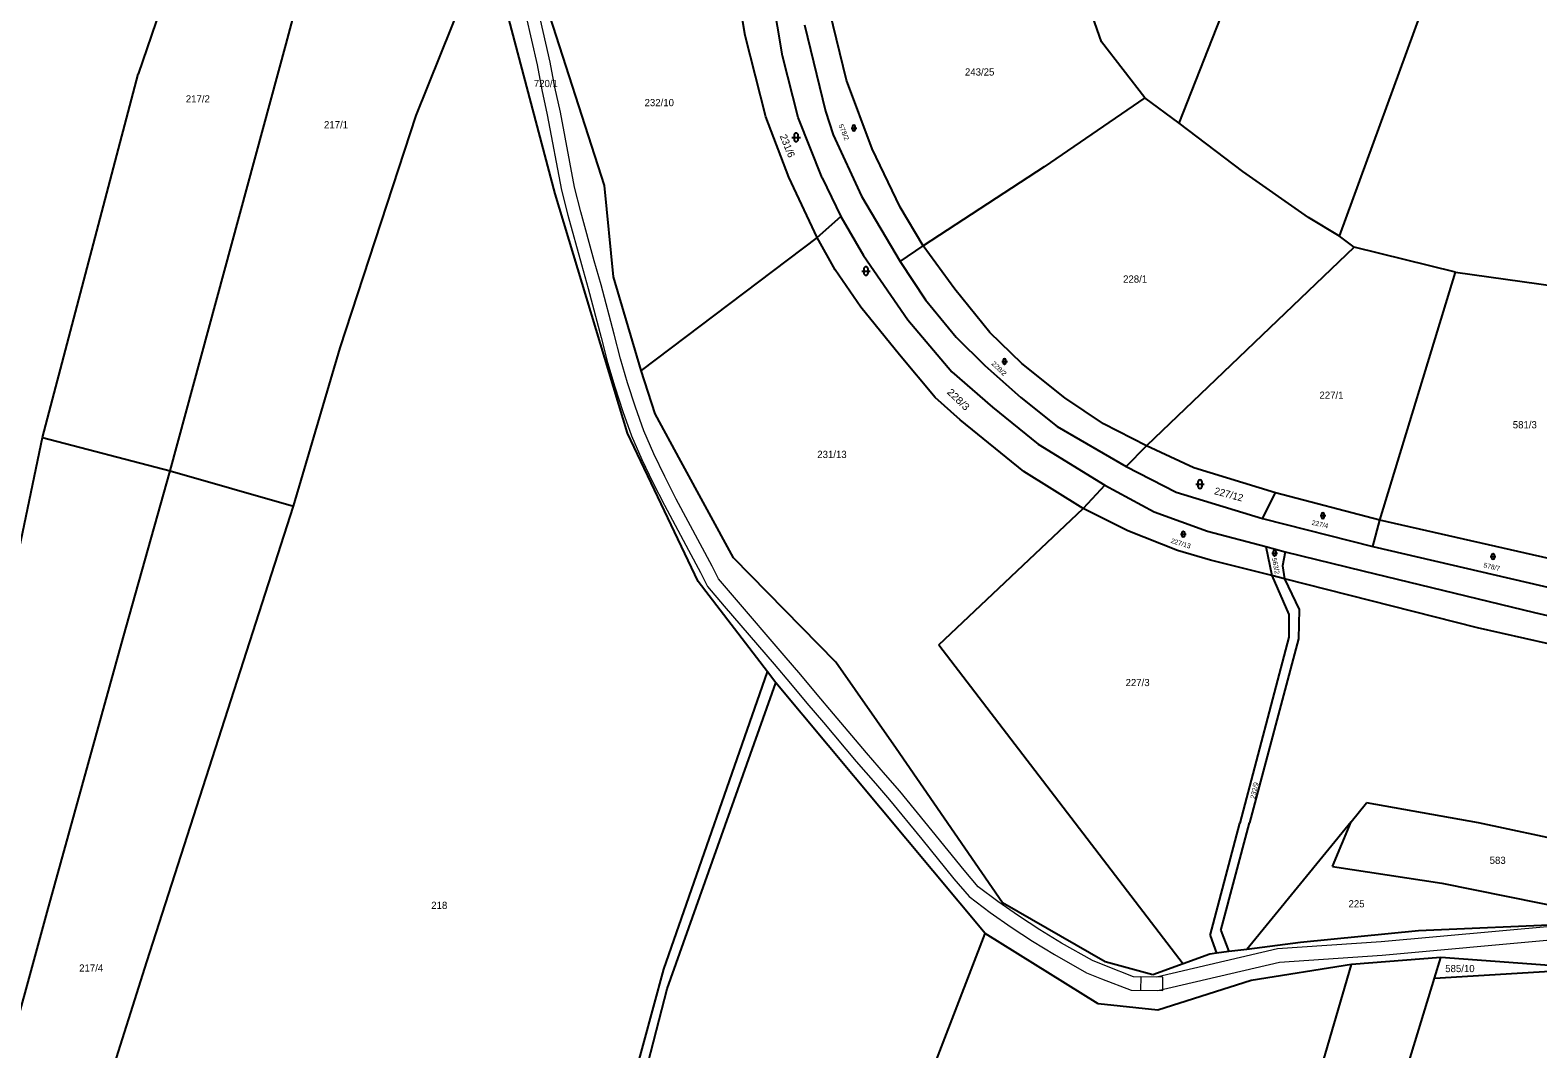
# Model space of a CAD drawing. Extents: x -701211 to -698780, y -1014269 to -1012378.
# Drawn here: x -701029.9 to -700673.2, y -1013179.3 to -1012938.3 of the extents above; entities that cross this region are included whole.
import ezdxf
from ezdxf.enums import TextEntityAlignment as Align

# ---------------------------------------------------------------- set-up
doc = ezdxf.new("R2010")
doc.units = 0
doc.header["$LTSCALE"] = 0.68
for name, color, linetype, lineweight in [('1', 7, 'Continuous', 25), ('13', 7, 'Continuous', 13), ('3', 7, 'Continuous', 25)]:
    doc.layers.add(name, color=color, linetype=linetype, lineweight=lineweight)
doc.layers.add('2', color=7, linetype='Continuous')

msp = doc.modelspace()

# ---------------------------------------------------------------- linework, layer by layer
at = {"layer": '1'}
for p, q in [((-700758.04, -1012960.3), (-700727.83, -1012883.45)), ((-700860.7, -1012939.55), (-700868.99, -1012890.01)), ((-700987.06, -1012897.76), (-701004.28, -1012948.73)), ((-700720.09, -1012987.07), (-700687.77, -1012898.43)), ((-700776.39, -1012941.06), (-700788.72, -1012906.25)), ((-700894, -1012975.02), (-700914.53, -1012911.43)), ((-700938.57, -1012958.49), (-700921.68, -1012916.49)), ((-700905.7, -1012977.03), (-700921.68, -1012916.49)), ((-700851.85, -1012944.35), (-700856.53, -1012916.78)), ((-700836.72, -1012950.14), (-700840.69, -1012933.93)), ((-700855.84, -1012958.82), (-700860.7, -1012939.55)), ((-700846.71, -1012937.05), (-700841.75, -1012957.5)), ((-700766.16, -1012954.34), (-700776.39, -1012941.06)), ((-700848.15, -1012958.95), (-700851.85, -1012944.35)), ((-701026.92, -1013034.65), (-701004.28, -1012948.73)), ((-700830.69, -1012966.36), (-700836.72, -1012950.14)), ((-700766.16, -1012954.34), (-700789.95, -1012970.64)), ((-700758.04, -1012960.3), (-700766.16, -1012954.34)), ((-700956.52, -1013013.46), (-700938.57, -1012958.49)), ((-700850.35, -1012973.06), (-700855.84, -1012958.82)), ((-700842.48, -1012973.27), (-700848.15, -1012958.95)), ((-700841.75, -1012957.5), (-700839.86, -1012963.08)), ((-700742.97, -1012971.7), (-700758.04, -1012960.3)), ((-700839.86, -1012963.08), (-700833.2, -1012977.59)), ((-700824.03, -1012980.14), (-700830.69, -1012966.36)), ((-700789.95, -1012970.64), (-700818.62, -1012989.33)), ((-700727.44, -1012982.58), (-700742.97, -1012971.7)), ((-700891.83, -1012996.63), (-700894, -1012975.02)), ((-700843.68, -1012987.38), (-700850.35, -1012973.06)), ((-700842.48, -1012973.27), (-700838.07, -1012982.37)), ((-700888.56, -1013033.61), (-700905.7, -1012977.03)), ((-700833.2, -1012977.59), (-700824.01, -1012993)), ((-700843.68, -1012987.38), (-700838.07, -1012982.37)), ((-700838.07, -1012982.37), (-700832.75, -1012991.62)), ((-700720.09, -1012987.07), (-700727.44, -1012982.58)), ((-700843.68, -1012987.38), (-700885.35, -1013018.79)), ((-700839.45, -1012995.03), (-700843.68, -1012987.38)), ((-700811.15, -1012999.6), (-700818.62, -1012989.33)), ((-700716.68, -1012989.67), (-700720.09, -1012987.07)), ((-700832.75, -1012991.62), (-700822.22, -1013006.85)), ((-700824.01, -1012993), (-700818.07, -1013002.06)), ((-700716.68, -1012989.67), (-700765.76, -1013036.63)), ((-700692.69, -1012995.55), (-700716.68, -1012989.67)), ((-700885.35, -1013018.79), (-700891.83, -1012996.63)), ((-700833.33, -1013003.86), (-700839.45, -1012995.03)), ((-700710.55, -1013054.2), (-700692.69, -1012995.55)), ((-700692.69, -1012995.55), (-700648.95, -1013001.61)), ((-700802.86, -1013009.78), (-700811.15, -1012999.6)), ((-700818.07, -1013002.06), (-700810.78, -1013010.89)), ((-700824.24, -1013015.12), (-700833.33, -1013003.86)), ((-700822.22, -1013006.85), (-700811.86, -1013019.09)), ((-700810.78, -1013010.89), (-700804.02, -1013017.65)), ((-700795.3, -1013017.17), (-700802.86, -1013009.78)), ((-700967.57, -1013050.91), (-700956.52, -1013013.46)), ((-700815.77, -1013025.2), (-700824.24, -1013015.12)), ((-700804.02, -1013017.65), (-700795.47, -1013025.22)), ((-700785.12, -1013025.28), (-700795.3, -1013017.17)), ((-700882.02, -1013029.05), (-700885.35, -1013018.79)), ((-700811.86, -1013019.09), (-700802.22, -1013027.47)), ((-700809.83, -1013030.51), (-700815.77, -1013025.2)), ((-700795.47, -1013025.22), (-700786.91, -1013032.07)), ((-700802.22, -1013027.47), (-700791.41, -1013036.21)), ((-700775.93, -1013031.4), (-700785.12, -1013025.28)), ((-700875.9, -1013040.22), (-700882.02, -1013029.05)), ((-700794.8, -1013042.67), (-700809.83, -1013030.51)), ((-700786.91, -1013032.07), (-700770.61, -1013041.53)), ((-700765.76, -1013036.63), (-700775.93, -1013031.4)), ((-701037.51, -1013084.94), (-701026.92, -1013034.65)), ((-701026.92, -1013034.65), (-700996.75, -1013042.57)), ((-700871.86, -1013068.73), (-700888.56, -1013033.61)), ((-700791.41, -1013036.21), (-700775.65, -1013045.94)), ((-700770.61, -1013041.53), (-700765.76, -1013036.63)), ((-700754.59, -1013041.86), (-700765.76, -1013036.63)), ((-701007.88, -1013082.07), (-700996.75, -1013042.57)), ((-700996.75, -1013042.57), (-700967.57, -1013050.91)), ((-700863.47, -1013063.1), (-700875.9, -1013040.22)), ((-700780.79, -1013051.47), (-700794.8, -1013042.67)), ((-700770.61, -1013041.53), (-700758.77, -1013047.55)), ((-700735.23, -1013047.71), (-700754.59, -1013041.86)), ((-700775.65, -1013045.94), (-700780.79, -1013051.47)), ((-700775.65, -1013045.94), (-700763.95, -1013052.25)), ((-700758.77, -1013047.55), (-700738.32, -1013053.85)), ((-700738.32, -1013053.85), (-700735.23, -1013047.71)), ((-700710.55, -1013054.2), (-700735.23, -1013047.71)), ((-701002.24, -1013158.7), (-700967.57, -1013050.91)), ((-700814.87, -1013083.67), (-700780.79, -1013051.47)), ((-700770.22, -1013056.72), (-700780.79, -1013051.47)), ((-700763.95, -1013052.25), (-700751.34, -1013056.84)), ((-700758.42, -1013061.4), (-700770.22, -1013056.72)), ((-700751.34, -1013056.84), (-700737.55, -1013060.42)), ((-700738.32, -1013053.85), (-700712.2, -1013060.43)), ((-700712.2, -1013060.43), (-700710.55, -1013054.2)), ((-700660.84, -1013065.55), (-700710.55, -1013054.2)), ((-700737.55, -1013060.42), (-700736.13, -1013067.31)), ((-700737.55, -1013060.42), (-700732.96, -1013061.68)), ((-700712.2, -1013060.43), (-700661.94, -1013072.14)), ((-700839.25, -1013087.78), (-700863.47, -1013063.1)), ((-700750.59, -1013063.65), (-700758.42, -1013061.4)), ((-700736.13, -1013067.31), (-700750.59, -1013063.65)), ((-700732.96, -1013061.68), (-700733.59, -1013065.02)), ((-700732.96, -1013061.68), (-700714.59, -1013066.21)), ((-700733.13, -1013068.07), (-700736.13, -1013067.31)), ((-700736.13, -1013067.31), (-700732.06, -1013076.53)), ((-700733.59, -1013065.02), (-700733.13, -1013068.07)), ((-700714.59, -1013066.21), (-700673.98, -1013076.04)), ((-700855.43, -1013090.08), (-700871.86, -1013068.73)), ((-700733.13, -1013068.07), (-700729.63, -1013075.36)), ((-700687.43, -1013079.64), (-700733.13, -1013068.07)), ((-700732.06, -1013076.53), (-700732.06, -1013081.85)), ((-700729.63, -1013075.36), (-700729.81, -1013082.3)), ((-700673.98, -1013076.04), (-700602.11, -1013092.88)), ((-701025.84, -1013146.92), (-701007.88, -1013082.07)), ((-700732.06, -1013081.85), (-700743.67, -1013125.89)), ((-700729.81, -1013082.3), (-700741.42, -1013125.8)), ((-700630.58, -1013092.65), (-700687.43, -1013079.64)), ((-700814.87, -1013083.67), (-700757.1, -1013159.17)), ((-700825.03, -1013108.22), (-700839.25, -1013087.78)), ((-700879.94, -1013160.4), (-700855.43, -1013090.08)), ((-700879.13, -1013165.07), (-700853.45, -1013092.71)), ((-700853.45, -1013092.71), (-700855.43, -1013090.08)), ((-700803.97, -1013151.99), (-700853.45, -1013092.71)), ((-700799.83, -1013144.7), (-700825.03, -1013108.22)), ((-700717.35, -1013125.54), (-700713.75, -1013121.04)), ((-700687.22, -1013125.82), (-700713.75, -1013121.04)), ((-700750.7, -1013152.46), (-700743.67, -1013125.89)), ((-700748.17, -1013151.29), (-700741.42, -1013125.8)), ((-700717.35, -1013125.54), (-700742.07, -1013155.75)), ((-700721.76, -1013136.17), (-700717.35, -1013125.54)), ((-700660.99, -1013131.4), (-700687.22, -1013125.82)), ((-700721.76, -1013136.17), (-700695.92, -1013140.04)), ((-700695.92, -1013140.04), (-700651.1, -1013149.11)), ((-700775.52, -1013158.66), (-700799.83, -1013144.7)), ((-701055.38, -1013254.89), (-701025.84, -1013146.92)), ((-700651.1, -1013149.11), (-700701.42, -1013151.36)), ((-700822.65, -1013200.55), (-700803.97, -1013151.99)), ((-700777.22, -1013168.6), (-700803.97, -1013151.99)), ((-700750.7, -1013152.46), (-700749.22, -1013156.66)), ((-700748.17, -1013151.29), (-700746.26, -1013156.28)), ((-700701.42, -1013151.36), (-700729.33, -1013154.15)), ((-700750.76, -1013156.85), (-700757.1, -1013159.17)), ((-700749.22, -1013156.66), (-700750.76, -1013156.85)), ((-700746.26, -1013156.28), (-700749.22, -1013156.66)), ((-700742.07, -1013155.75), (-700746.26, -1013156.28)), ((-700729.33, -1013154.15), (-700742.07, -1013155.75)), ((-701034.91, -1013261.81), (-701002.24, -1013158.7)), ((-700893.14, -1013208.9), (-700879.94, -1013160.4)), ((-700764.26, -1013161.8), (-700775.52, -1013158.66)), ((-700757.1, -1013159.17), (-700764.26, -1013161.8)), ((-700717.26, -1013159.31), (-700741.03, -1013163.12)), ((-700732.05, -1013209.73), (-700717.26, -1013159.31)), ((-700697.67, -1013162.55), (-700660.45, -1013160.31)), ((-700660.45, -1013160.31), (-700696.15, -1013157.65)), ((-700741.03, -1013163.12), (-700763.12, -1013170.13)), ((-700890.63, -1013209.17), (-700879.13, -1013165.07)), ((-700763.12, -1013170.13), (-700777.22, -1013168.6))]:
    msp.add_line(p, q, dxfattribs=at)
for points in [[(-700996.75, -1013042.57), (-700969.3, -1012941.55), (-700948.79, -1012864.57)], [(-700824.01, -1012993), (-700818.62, -1012989.33), (-700824.03, -1012980.14)], [(-700712.56, -1013211.36), (-700697.67, -1013162.55), (-700696.15, -1013157.65), (-700717.26, -1013159.31)]]:
    msp.add_lwpolyline(points, dxfattribs=at)
at = {"layer": '13'}
for points in [[(-700912.64, -1012934.83), (-700909.96, -1012946.54), (-700908.81, -1012952.44), (-700907.54, -1012958.34), (-700904.14, -1012976.15), (-700902.64, -1012982.04), (-700899.46, -1012993.74), (-700897.86, -1012999.39), (-700894.75, -1013011.02), (-700893.25, -1013016.89), (-700891.54, -1013022.69), (-700889.67, -1013028.47), (-700887.64, -1013034.25), (-700885.16, -1013039.83), (-700882.55, -1013045.3), (-700879.82, -1013050.7), (-700874.16, -1013061.3), (-700871.32, -1013066.59), (-700869.64, -1013069.87)], [(-700869.64, -1013069.87), (-700865.67, -1013074.58), (-700853.88, -1013088.26), (-700849.97, -1013092.86), (-700846.12, -1013097.49), (-700842.18, -1013102.07), (-700834.43, -1013111.3), (-700829.88, -1013116.5), (-700826.56, -1013120.35), (-700818.92, -1013129.66), (-700811.32, -1013139.05), (-700807.74, -1013143.27), (-700802.78, -1013146.98), (-700797.8, -1013150.46), (-700792.71, -1013153.82), (-700787.51, -1013156.96), (-700779.96, -1013161.25), (-700776.42, -1013162.68), (-700769.41, -1013165.38), (-700761.93, -1013165.46), (-700761.89, -1013162.3), (-700768.81, -1013162.22), (-700775.26, -1013159.74), (-700778.58, -1013158.39), (-700785.91, -1013154.24), (-700791.03, -1013151.14), (-700796.02, -1013147.84), (-700800.92, -1013144.42), (-700805.56, -1013140.95), (-700808.88, -1013137.03), (-700816.48, -1013127.66), (-700824.14, -1013118.31), (-700827.5, -1013114.42), (-700832.03, -1013109.24), (-700839.78, -1013100.03), (-700843.7, -1013095.45), (-700847.55, -1013090.82), (-700851.48, -1013086.2), (-700863.27, -1013072.54), (-700867, -1013068.11), (-700868.52, -1013065.13), (-700871.38, -1013059.8), (-700877.02, -1013049.24), (-700879.71, -1013043.9), (-700882.3, -1013038.51), (-700884.7, -1013033.09), (-700886.67, -1013027.47), (-700888.52, -1013021.75), (-700890.21, -1013016.05), (-700891.69, -1013010.22), (-700894.82, -1012998.55), (-700896.42, -1012992.9), (-700899.58, -1012981.24), (-700901.06, -1012975.47), (-700904.44, -1012957.72), (-700905.71, -1012951.8), (-700906.86, -1012945.88), (-700909.56, -1012934.11)], [(-700669.27, -1013150.25), (-700710.28, -1013153.93), (-700734.78, -1013155.59), (-700763.42, -1013162.3), (-700767.1, -1013162.22), (-700767.17, -1013165.38), (-700763.09, -1013165.47), (-700734.3, -1013158.73), (-700710.03, -1013157.08), (-700669.29, -1013153.42)]]:
    msp.add_lwpolyline(points, dxfattribs=at)
at = {"layer": '3'}
for p, q in [((-700849.661, -1012963.661), (-700847.659, -1012963.661)), ((-700849.161, -1012963.161), (-700849.161, -1012964.162)), ((-700848.159, -1012964.162), (-700848.159, -1012963.161)), ((-700835.661, -1012961.461), (-700834.319, -1012961.461)), ((-700835.325, -1012961.125), (-700835.325, -1012961.796)), ((-700834.655, -1012961.796), (-700834.655, -1012961.125)), ((-700833.151, -1012995.271), (-700831.149, -1012995.271)), ((-700832.651, -1012994.771), (-700832.651, -1012995.772)), ((-700831.649, -1012995.772), (-700831.649, -1012994.771)), ((-700800.031, -1013016.691), (-700798.689, -1013016.691)), ((-700799.695, -1013016.355), (-700799.695, -1013017.026)), ((-700799.025, -1013017.026), (-700799.025, -1013016.355)), ((-700754.121, -1013045.691), (-700752.119, -1013045.691)), ((-700753.621, -1013045.191), (-700753.621, -1013046.192)), ((-700752.619, -1013046.192), (-700752.619, -1013045.191)), ((-700724.711, -1013053.131), (-700723.369, -1013053.131)), ((-700724.375, -1013052.795), (-700724.375, -1013053.466)), ((-700723.705, -1013053.466), (-700723.705, -1013052.795)), ((-700757.395, -1013057.185), (-700757.395, -1013057.856)), ((-700756.725, -1013057.856), (-700756.725, -1013057.185)), ((-700757.731, -1013057.521), (-700756.389, -1013057.521)), ((-700736.121, -1013062.021), (-700734.779, -1013062.021)), ((-700735.785, -1013061.685), (-700735.785, -1013062.356)), ((-700735.115, -1013062.356), (-700735.115, -1013061.685)), ((-700684.451, -1013062.791), (-700683.109, -1013062.791)), ((-700684.115, -1013062.455), (-700684.115, -1013063.126)), ((-700683.445, -1013063.126), (-700683.445, -1013062.455))]:
    msp.add_line(p, q, dxfattribs=at)
for centre, radius, start, end in [((-700834.99, -1012961.1256), 0.335, 0, 180), ((-700848.66, -1012963.1609), 0.5, 0, 180), ((-700848.66, -1012964.1609), 0.5, 180, 359.98789), ((-700834.99, -1012961.7956), 0.335, 180, 359.98789), ((-700832.15, -1012994.7709), 0.5, 0, 180), ((-700832.15, -1012995.7709), 0.5, 180, 359.98789), ((-700799.36, -1013016.3556), 0.335, 0, 180), ((-700799.36, -1013017.0256), 0.335, 180, 359.98789), ((-700753.12, -1013045.1909), 0.5, 0, 180), ((-700753.12, -1013046.1909), 0.5, 180, 359.98789), ((-700724.04, -1013052.7956), 0.335, 0, 180), ((-700724.04, -1013053.4656), 0.335, 180, 359.98789), ((-700757.06, -1013057.1856), 0.335, 0, 180), ((-700757.06, -1013057.8556), 0.335, 180, 359.98789), ((-700735.45, -1013061.6856), 0.335, 0, 180), ((-700735.45, -1013062.3556), 0.335, 180, 359.98789), ((-700683.78, -1013062.4556), 0.335, 0, 180), ((-700683.78, -1013063.1256), 0.335, 180, 359.98789)]:
    msp.add_arc(centre, radius, start, end, dxfattribs=at)

# ---------------------------------------------------------------- texts
at = {"layer": '2'}
for s, p in [('720/1', (-700910.71, -1012951.765)), ('585/10', (-700695.1, -1013161.125))]:
    msp.add_text(s, height=1.7, dxfattribs=at).set_placement(p)
for s, p in [('243/25', (-700805.24, -1012949.035)), ('217/2', (-700990.2, -1012955.405)), ('232/10', (-700881.04, -1012956.285)), ('217/1', (-700957.51, -1012961.515)), ('228/1', (-700768.46, -1012998.025)), ('227/1', (-700722.01, -1013025.495)), ('581/3', (-700676.27, -1013032.485)), ('231/13', (-700840.18, -1013039.505)), ('227/3', (-700767.87, -1013093.465)), ('583', (-700682.689, -1013135.515)), ('218', (-700933.079, -1013146.175)), ('225', (-700716.079, -1013145.805)), ('217/4', (-701015.43, -1013160.995))]:
    msp.add_text(s, height=1.7, dxfattribs=at).set_placement(p, align=Align.CENTER)
for s, height, rotation, width, p in [('578/2', 1.14, 293, 1.05, (-700837.8837, -1012962.6543)), ('228/2', 1.14, 316, 1.1, (-700801.0465, -1013018.7487)), ('228/3', 1.7, 316, 1.1, (-700810.8645, -1013026.2652))]:
    msp.add_text(s, height=height, rotation=rotation, dxfattribs=dict(at, width=width)).set_placement(p, align=Align.CENTER)
for s, height, rotation, p in [('231/6', 1.7, 292, (-700851.4981, -1012965.9806)), ('227/12', 1.7, 345, (-700746.508, -1013048.9301)), ('227/4', 1.14, 347, (-700724.8487, -1013055.7219)), ('227/13', 1.14, 343, (-700757.8182, -1013060.2476)), ('563/2', 1.14, 281, (-700735.7384, -1013065.1492)), ('578/7', 1.14, 347, (-700684.1887, -1013065.8019)), ('232/9', 1.14, 77, (-700739.6871, -1013118.2687))]:
    msp.add_text(s, height=height, rotation=rotation, dxfattribs=at).set_placement(p, align=Align.CENTER)

doc.saveas('drawing.dxf')
